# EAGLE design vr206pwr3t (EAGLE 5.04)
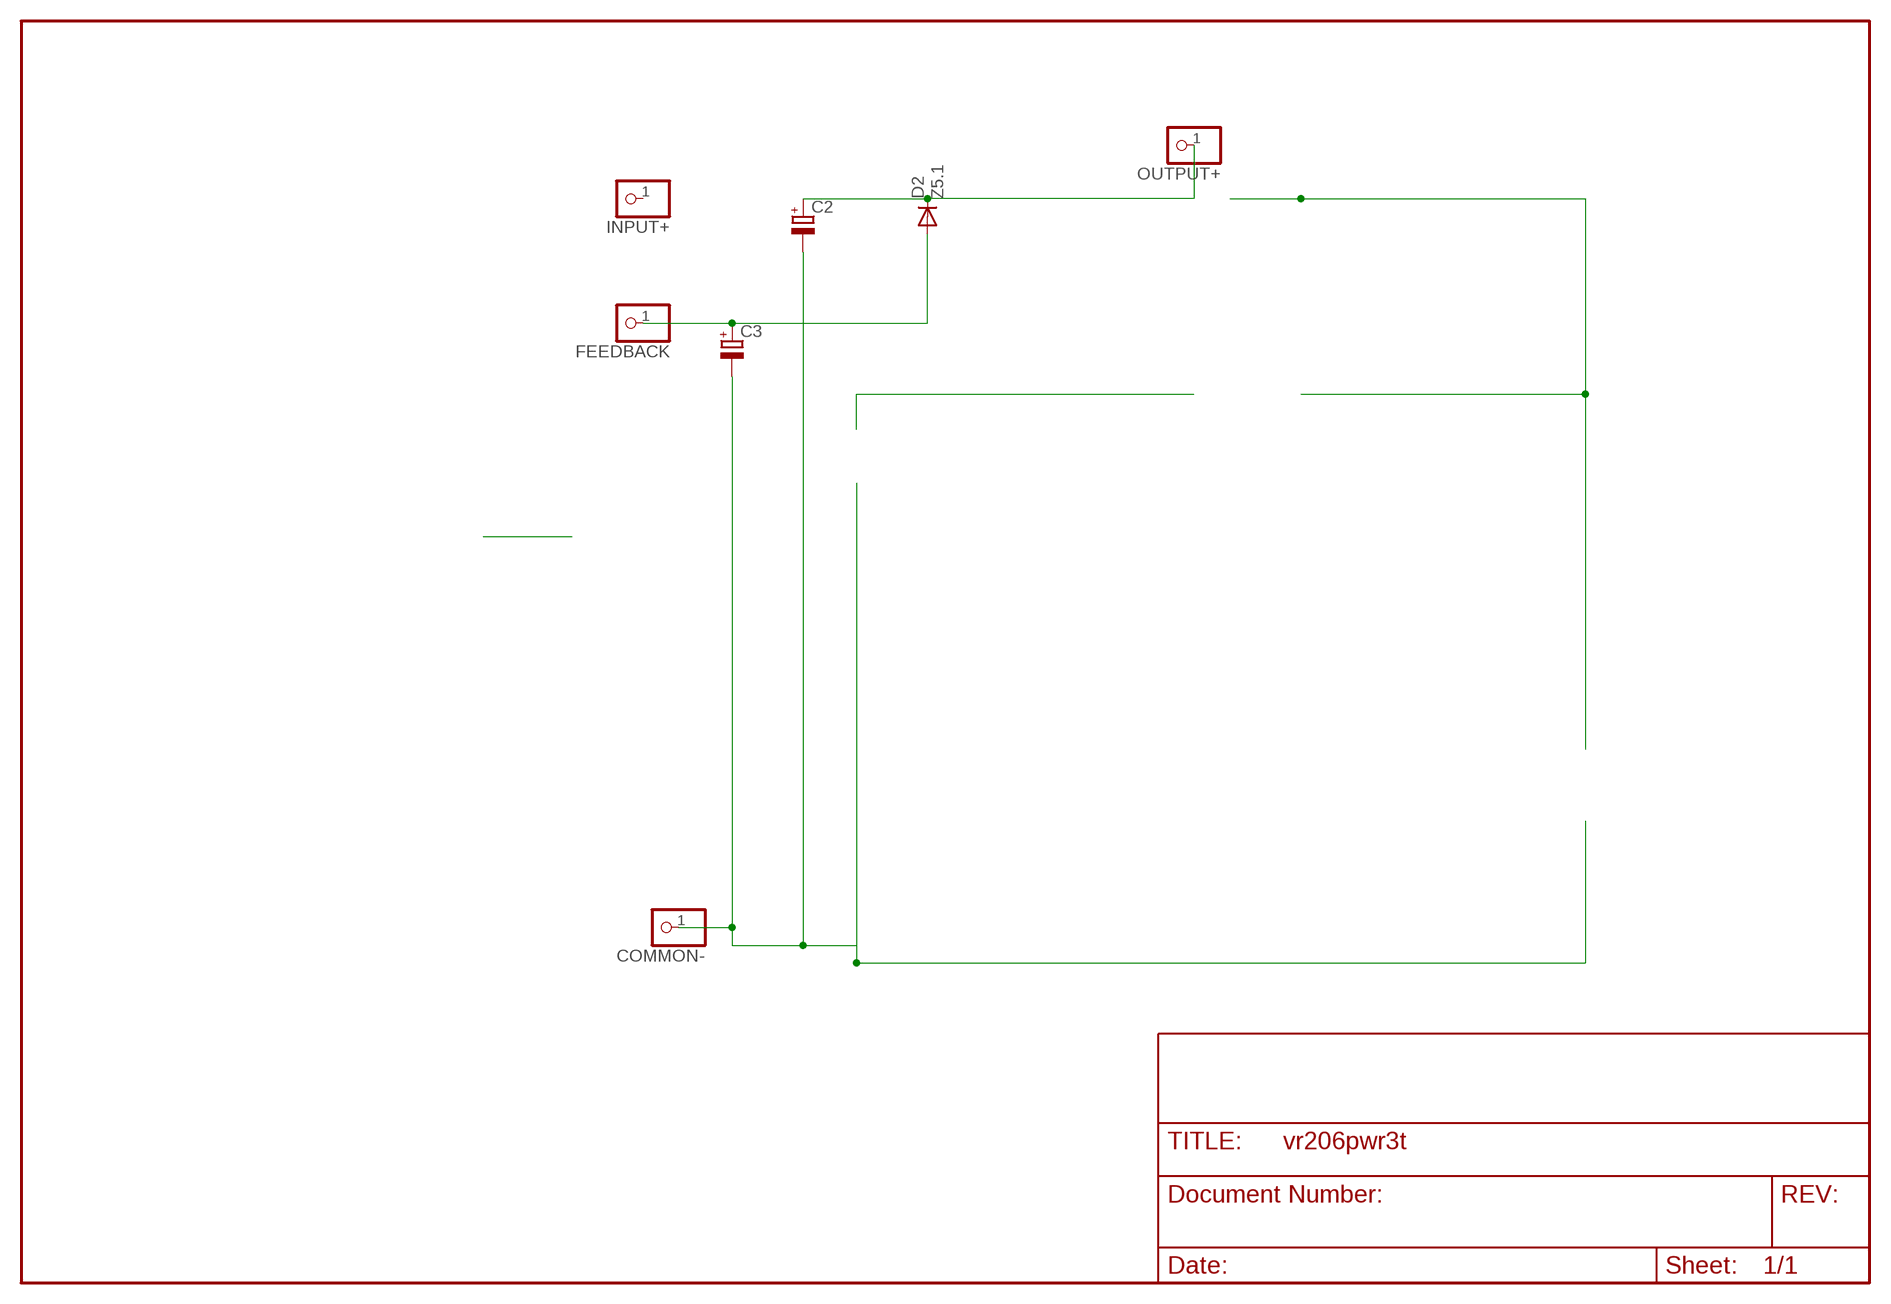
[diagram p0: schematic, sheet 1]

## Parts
C2  CPOL-EUE2.5-7  [E2,5-7]
C3  CPOL-EUE2-4  [E2-4]
COMMON-  PINHD-1X1  [1X01]
D2  Z5.1  DIODE-D-2.5  [D-2.5]
FEEDBACK  PINHD-1X1  [1X01]
INPUT+  PINHD-1X1  [1X01]
OUTPUT+  PINHD-1X1  [1X01]

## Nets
LOAD: C2.+ D2.C OUTPUT+.1
N$4: C3.+ D2.A FEEDBACK.1
N$30: C2.- C3.- COMMON-.1
Unconnected: INPUT+.1

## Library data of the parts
C2 C3 = rcl(2):CPOL-EU: POLARIZED CAPACITOR, European symbol
COMMON- FEEDBACK INPUT+ OUTPUT+ = pinhead:PINHD-1X1: PIN HEADER
D2 = diode:DIODE-: DIODE

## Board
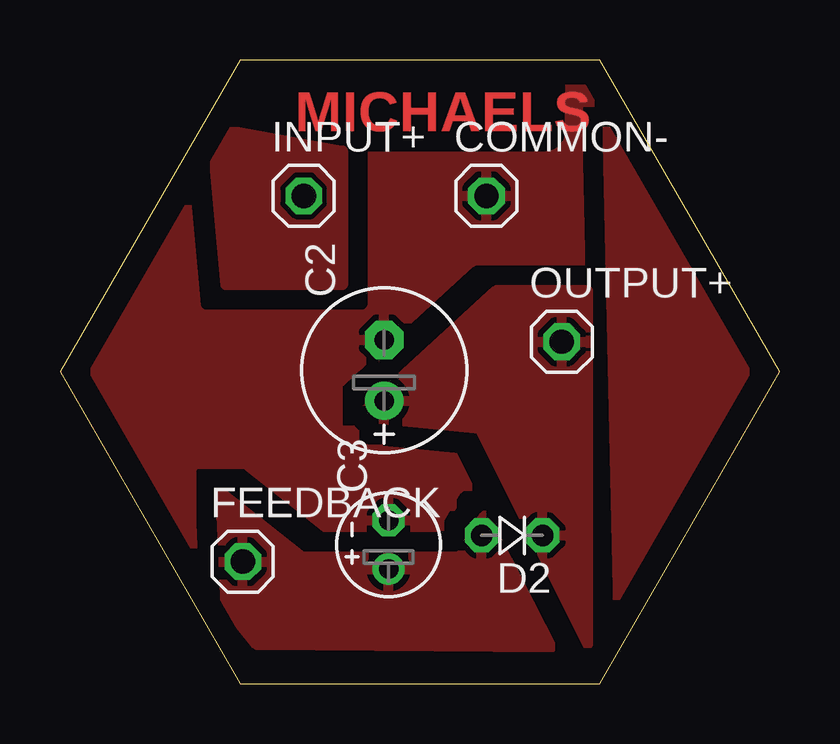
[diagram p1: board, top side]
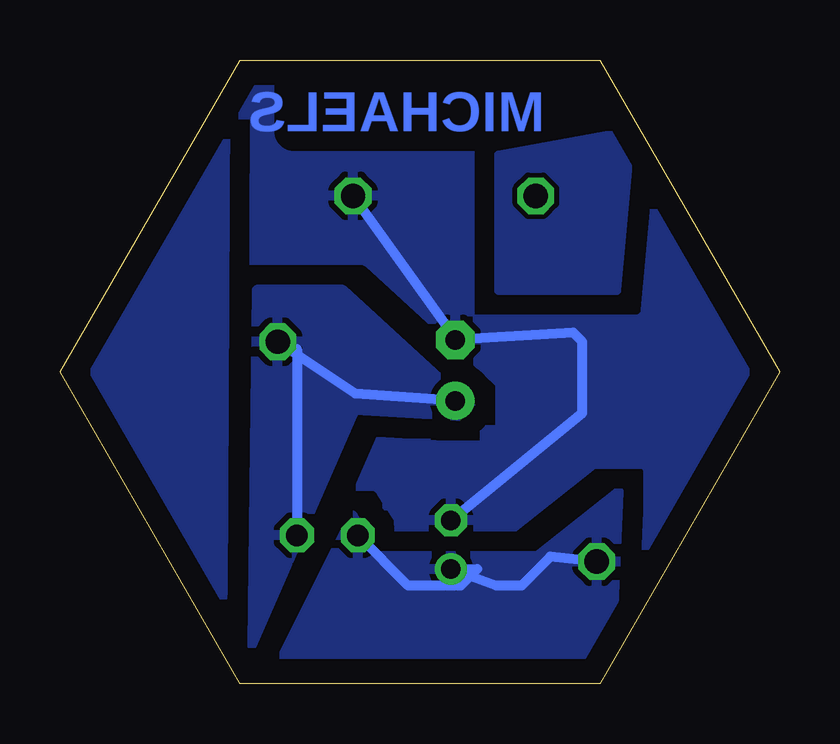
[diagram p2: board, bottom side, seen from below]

Size 30 x 25.98 mm. Coordinates in mm from the lower left corner, seen from the top.
Outline: 7.5,0 22.5,0 30,12.99 22.5,25.98 7.5,25.98 0,12.99 7.5,0
Copper layers (1*16): Top 0.035mm / dielectric 1.5mm / Bottom 0.035mm
Design rules "default": minimum track width 10mil, minimum drill 24mil, track to track 8mil, track to pad 8mil, pad to pad 8mil, via to via 8mil, smd to smd 8mil, copper to edge 40mil, drill to drill 8mil, minimum pad ring 10mil, minimum via ring 8mil, stop-mask expansion 4mil, vias tented up to drill 0mil, thermal gap 10mil

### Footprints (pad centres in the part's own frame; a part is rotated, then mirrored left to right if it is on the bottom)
E2,5-7 = drill 0.813 pad 1.6 round: + -1.27,0 | drill 0.813 pad 1.6 octagon: - 1.27,0
E2-4 = drill 0.813 pad 1.27 round: + -1.016,0 | drill 0.813 pad 1.27 octagon: - 1.016,0
1X01 = drill 1.016 octagon: 1 0,0
D-2.5 = drill 0.9 octagon: A 1.27,0; C -1.27,0

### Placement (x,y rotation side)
C2  13.52,13.05 90 top
C3  13.7,5.78 90 top
COMMON-  17.78,20.32 0 top
D2  18.85,6.18 180 top
FEEDBACK  7.62,5.08 0 top
INPUT+  10.16,20.32 0 top
OUTPUT+  20.92,14.24 0 top

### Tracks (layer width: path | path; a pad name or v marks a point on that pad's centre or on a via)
LOAD
  Bottom 0.406: D2.C 20.12,13.94 OUTPUT+.1 17.68,12.08 C2.+
  pour Bottom: 18.2,16.4 21.8,16.4 22,1.6 17.7,11.4 12.4,11.1
  pour Top: 18.2,16.4 22,16.4 22,1.6 17.5,10.6 12.4,11.1
N$1
  pour Top: 11.8,16.6 6.9,16.6 6.3,23.2 11.8,22.2
  pour Bottom: 11.7,16.4 6.8,16.4 6.2,23 11.7,22
  pour Top (rank 2): 23.3,2.1 22.8,24.4 29.3,12.9 27,7.2
  pour Bottom (rank 2): 23.4,2.1 23.2,3.8 23.1,24.1 29.5,12.9 27,7.2
N$4
  Bottom 0.406: FEEDBACK.1 9.55,5.29 10.76,4.08 11.81,4.08 C3.+ 12.6,4.78 13.3,4.08 15.48,4.08 D2.A
  pour Bottom: 6.7,8 10.1,5.3 16.7,5.3 17.8,7 21.1,0.4 8.3,0.6 6.9,3.2
  pour Top: 6.7,8 10.1,5.3 16.7,5.3 17.7,7 20.5,1.5 8.2,1.6 6.9,3.2
N$30
  Bottom 0.406: COMMON-.1 13.68,14.62 C2.- 8.6,14.62 8.22,14.24 8.22,11.28 C3.-
  pour Bottom (isolate 0.813, rank 3): 7.6,26.5 23.9,26.5 29.8,13 23.2,0.7 8.2,0.8 -0.3,14.5 6.3,26.2
  pour Top (isolate 0.813, rank 3): 6.8,26.4 23.1,26.4 29.6,12.8 23.2,0.7 8.2,0.8 -0.3,14.5 6.3,26.2

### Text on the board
Top: MICHAELS
Bottom: MICHAELS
